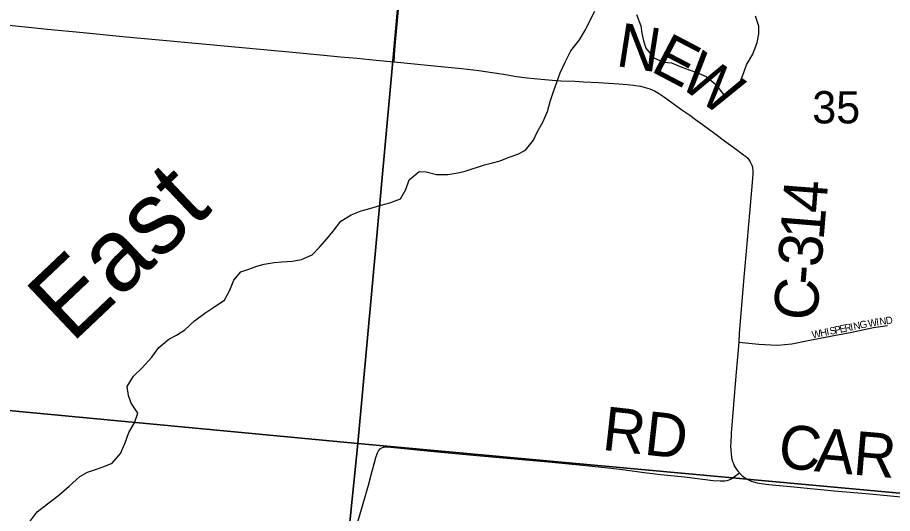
# Model space of a CAD drawing. Extents: x 1410790 to 1770854, y 566777 to 831614.
# Drawn here: x 1564816 to 1570818, y 706232 to 709632 of the extents above; entities that cross this region are included whole.
import ezdxf

# ---------------------------------------------------------------- set-up
doc = ezdxf.new("R2010")
doc.units = 0
for name, color, linetype in [('GM_X_County_Road', 7, 'Continuous'), ('GM_X_County_Road_Text', 7, 'Continuous'), ('GM_X_Minor_River', 7, 'Continuous'), ('GM_X_Minor_River_Text', 7, 'Continuous'), ('GM_X_Section', 7, 'Continuous'), ('GM_X_Section_Text', 7, 'Continuous'), ('GM_X_Township_Road', 7, 'Continuous'), ('GM_X_Township_Road_Text', 7, 'Continuous'), ('GM_X_Township_Subdivision', 7, 'Continuous'), ('GM_X_Township_Subdivision_Text', 7, 'Continuous')]:
    doc.layers.add(name, color=color, linetype=linetype)

msp = doc.modelspace()

# ---------------------------------------------------------------- linework, layer by layer
at = {"layer": 'GM_X_County_Road'}
for points in [[(1567399.9, 709328.4), (1567405.5, 709411.7), (1567439.3, 709786.8), (1567473.1, 710145.6), (1567484.9, 710276.2), (1567501.2, 710455.7), (1567530.6, 710782), (1567544, 710928.8), (1567559.1, 711092), (1567583.2, 711369.5), (1567627.9, 711875.4), (1567635.1, 711954), (1567635.2, 711955.3)], [(1562912.1, 709751.8), (1563016, 709741.8), (1563179.3, 709726.2), (1563440.7, 709702.8), (1563653, 709683.3), (1563767.4, 709673.9), (1563865.4, 709666.4), (1564207.6, 709637.7), (1564289.1, 709630.3), (1564386.8, 709619.9), (1564533.5, 709602.9), (1564713, 709584.6), (1564892.3, 709566), (1565022.8, 709552.4), (1565267.7, 709528.8), (1565561.6, 709500.5), (1565839.2, 709474.4), (1566753.6, 709389.4), (1566916.9, 709374.1), (1567031.2, 709363.3), (1567145.5, 709352.8), (1567277.5, 709340.6), (1567399.9, 709328.4)], [(1567399.9, 709328.4), (1567674.2, 709300.2), (1567863.3, 709281.6), (1567980.3, 709268.5), (1568073.2, 709255.4), (1568149.7, 709243.4), (1568239.3, 709228), (1568313.1, 709218.2), (1568409.3, 709208.4), (1568459.6, 709204), (1568510.4, 709200.7), (1568544.1, 709199.1), (1568640.3, 709194.7), (1568698.4, 709192), (1568800.6, 709187.1), (1568940, 709178.3), (1568998.5, 709173.4), (1569041.6, 709168.4), (1569090.5, 709160.7), (1569122.7, 709153.1), (1569154.3, 709143), (1569184.8, 709129.6), (1569213.8, 709113.6), (1569255.2, 709086.4), (1569374.3, 709000.2), (1569427.1, 708961.9), (1569467.2, 708933.3), (1569546.8, 708874.9), (1569608.8, 708829.6), (1569666.5, 708787.6), (1569749.1, 708727.3), (1569797.2, 708691.9), (1569811.1, 708681.2), (1569825.8, 708667.1), (1569834.5, 708655.1), (1569843.1, 708642.6), (1569849.8, 708629.5), (1569854.8, 708615.5), (1569857.9, 708598.7), (1569859.7, 708580.2), (1569860, 708559.2), (1569858.1, 708530.2), (1569856, 708500.9), (1569851.5, 708448.6), (1569816.7, 708056.4), (1569800, 707876.8), (1569767.6, 707468.3), (1569763.2, 707406.1)], [(1569763.2, 707406.1), (1569744.3, 707174.8), (1569712.2, 706782.5), (1569708.3, 706717.2), (1569707.6, 706694.9), (1569708.5, 706668.4), (1569711.3, 706636.1), (1569717, 706604.4), (1569721.3, 706588.9), (1569726.7, 706573.9), (1569733.3, 706559.3), (1569741.1, 706545.3), (1569749.9, 706532), (1569759.7, 706519.2), (1569767.8, 706510)], [(1569767.8, 706510), (1569770.3, 706507.1), (1569781.7, 706495.9), (1569793.9, 706485.6), (1569806.9, 706476.1), (1569820.6, 706467.7), (1569834.8, 706460.3), (1569849.5, 706453.9), (1569864.6, 706448.6), (1569889.7, 706442.7), (1569917.4, 706437.7), (1569971.1, 706431), (1570141.2, 706415.3), (1570417.6, 706388.4), (1570662.6, 706366.2), (1570875, 706347.6), (1571152.8, 706323.6), (1571575.3, 706293), (1571748.5, 706278.8), (1572010.3, 706255.4), (1572223.4, 706235.6)]]:
    msp.add_lwpolyline(points, dxfattribs=at)
at = {"layer": 'GM_X_Minor_River'}
for points in [[(1568748.9, 709623.9), (1568777.6, 709675.8)], [(1569062.1, 709652.3), (1569091.3, 709575.7), (1569098.6, 709525.4), (1569110, 709473.1), (1569127.4, 709422.8), (1569180.7, 709355.9), (1569248.5, 709325), (1569302.6, 709320.3), (1569372.5, 709291.4), (1569424.4, 709272.7), (1569476.3, 709256), (1569540.1, 709227.2), (1569605.6, 709172.2), (1569658.9, 709105.4), (1569725.4, 709124.6), (1569770.2, 709184.3), (1569799.2, 709256.2), (1569817.9, 709308.2), (1569861, 709381.9), (1569890, 709459.8), (1569900.8, 709519.9), (1569901.5, 709572.1), (1569878.3, 709640.6)], [(1564902.8, 706180.6), (1564951.7, 706244.2), (1565022.6, 706299.6), (1565099.6, 706356.8), (1565170.6, 706420.2), (1565243.6, 706485.5), (1565296.1, 706515), (1565364.6, 706538.2), (1565414.9, 706555.7), (1565465.4, 706577.1), (1565522.3, 706642.7), (1565555.4, 706716.5), (1565580.3, 706788.4), (1565619.3, 706854.2), (1565642.2, 706920.1), (1565596.9, 706988.9), (1565577.5, 707041.3), (1565568.3, 707103.6), (1565611.3, 707173.3), (1565672.2, 707230.8), (1565737.3, 707304.2), (1565786.2, 707369.9), (1565855.1, 707427.2), (1565907.6, 707454.7), (1565964.3, 707492.1), (1566031.2, 707553.5), (1566100.1, 707604.9), (1566170.9, 707652.2), (1566235.6, 707695.5), (1566272.5, 707763.3), (1566299.5, 707831.2), (1566348.3, 707888.8), (1566402.7, 707906.2), (1566457.1, 707927.7), (1566507.4, 707941.1), (1566577.8, 707952.3), (1566630, 707957.7), (1566702.3, 707962.8), (1566764.6, 707974.1), (1566837.2, 708005.4), (1566890, 708060.9), (1566940.9, 708116.5), (1566981.6, 708168.2), (1567034.6, 708235.8), (1567105.4, 708279.1), (1567173.9, 708306.3), (1567232.3, 708323.7), (1567302.7, 708342.9), (1567371.2, 708362.2), (1567443.7, 708389.4), (1567480.6, 708453.2), (1567503.5, 708519.1), (1567570.4, 708576.5), (1567620.5, 708573.9), (1567690.5, 708557), (1567768.7, 708556), (1567837.1, 708567.3), (1567887.3, 708578.7), (1568020.2, 708621.3), (1568074.6, 708636.7), (1568126.9, 708650.1), (1568181.3, 708673.5), (1568247.8, 708694.8), (1568300.3, 708722.3), (1568355.3, 708791.8), (1568380.1, 708845.7), (1568419.1, 708915.5), (1568452.1, 708987.3), (1568469, 709057.4), (1568487.7, 709111.3), (1568516.8, 709189.2), (1568539.6, 709253.2), (1568574.7, 709331), (1568611.8, 709404.8), (1568670.9, 709478.4), (1568713.9, 709552.1), (1568748.9, 709623.9)]]:
    msp.add_lwpolyline(points, dxfattribs=at)
at = {"layer": 'GM_X_Section'}
for points in [[(1562327.3, 712402.7), (1567630.9, 711958.6), (1567151.7, 706711.5), (1561825.1, 707214)], [(1567630.9, 711958.6), (1572586.3, 711496.1), (1572215, 706247.2), (1567151.7, 706711.5)], [(1561825.1, 707214), (1567151.7, 706711.5), (1566597.6, 701281.7), (1561290.4, 701741.9)], [(1567151.7, 706711.5), (1572215, 706247.2), (1571988.9, 700698.1), (1566597.6, 701281.7)]]:
    msp.add_lwpolyline(points, close=True, dxfattribs=at)
at = {"layer": 'GM_X_Township_Road'}
msp.add_lwpolyline([(1567147.1, 706158), (1567183.4, 706284), (1567223, 706425.9), (1567240.1, 706489.1), (1567273.8, 706616.1), (1567284.8, 706647.7), (1567293.1, 706662.7), (1567305, 706675.7), (1567320.4, 706684.5), (1567326.3, 706685.9), (1567337.4, 706688.4), (1567354.5, 706688.6), (1567648.3, 706659.2), (1567942, 706632.8), (1568480.5, 706584.4), (1568692.5, 706563.5), (1568888.1, 706543.9), (1568985.7, 706531.1), (1569115.4, 706512.4), (1569229.2, 706500.1), (1569392.2, 706483), (1569587.9, 706459.2), (1569636.6, 706455.5), (1569652.6, 706455.4), (1569668.4, 706456.4), (1569683.7, 706458.8), (1569698.4, 706463.5), (1569712.1, 706470.8), (1569725.2, 706480), (1569767.8, 706510)], dxfattribs=at)
at = {"layer": 'GM_X_Township_Subdivision'}
msp.add_lwpolyline([(1569763.2, 707406.1), (1569901.7, 707392.8), (1569983, 707387.7), (1570031.8, 707387.1), (1570080.5, 707389.8), (1570128.9, 707395.9), (1570240.9, 707417.3), (1570416.5, 707451.6), (1570528.4, 707473), (1570687.8, 707506.1), (1570751.9, 707517.4), (1570784.1, 707521.7)], dxfattribs=at)

# ---------------------------------------------------------------- texts
at = {"layer": 'GM_X_County_Road_Text'}
for s, rotation, p in [('N', 351.07908, (1568914.6, 709301.2)), ('E', 332.34625, (1569150.9, 709268.3)), ('W', 324.18316, (1569340.1, 709170.1)), ('4', 85.56175, (1570360.4, 708285.4)), ('1', 85.30915, (1570345.2, 708099.7)), ('3', 85.21694, (1570329.7, 707915.1)), ('-', 85.19357, (1570319.4, 707792.2)), ('C', 85.19357, (1570298.8, 707546.6)), ('C', 353.75851, (1570025.7, 706549.9)), ('A', 355.02601, (1570277.8, 706522.4)), ('R', 355.08384, (1570541.2, 706499.5))]:
    msp.add_text(s, height=300, rotation=rotation, dxfattribs=at).set_placement(p)
at = {"layer": 'GM_X_Minor_River_Text'}
msp.add_text('East', height=500.18, rotation=43.42796, dxfattribs=at).set_placement((1565188.1, 707393.4))
at = {"layer": 'GM_X_Section_Text'}
msp.add_text('35', height=221, rotation=0.00001, dxfattribs=at).set_placement((1570267.8, 708906.2))
at = {"layer": 'GM_X_Township_Road_Text'}
msp.add_text('RD', height=300, rotation=353.60729, dxfattribs=at).set_placement((1568820.1, 706669.2))
at = {"layer": 'GM_X_Township_Subdivision_Text'}
for s, rotation, p in [('N', 11.43461, (1570555.1, 707489.8)), ('G', 11.41707, (1570598.2, 707498.6)), ('W', 9.88525, (1570653.9, 707509.8)), ('I', 8.11156, (1570709.9, 707519.6)), ('N', 7.98173, (1570731.6, 707522.7)), ('D', 7.99864, (1570775.2, 707528.8)), ('W', 11.42535, (1570270.3, 707432.4)), ('H', 11.39565, (1570326.4, 707443.7)), ('I', 11.44186, (1570369.6, 707452.4)), ('S', 11.41172, (1570391.1, 707456.7)), ('P', 11.4319, (1570425.6, 707463.7)), ('E', 11.41172, (1570460.1, 707470.7)), ('R', 11.41959, (1570494.6, 707477.7)), ('I', 11.39565, (1570533.5, 707485.5))]:
    msp.add_text(s, height=50, rotation=rotation, dxfattribs=at).set_placement(p)

doc.saveas('drawing.dxf')
